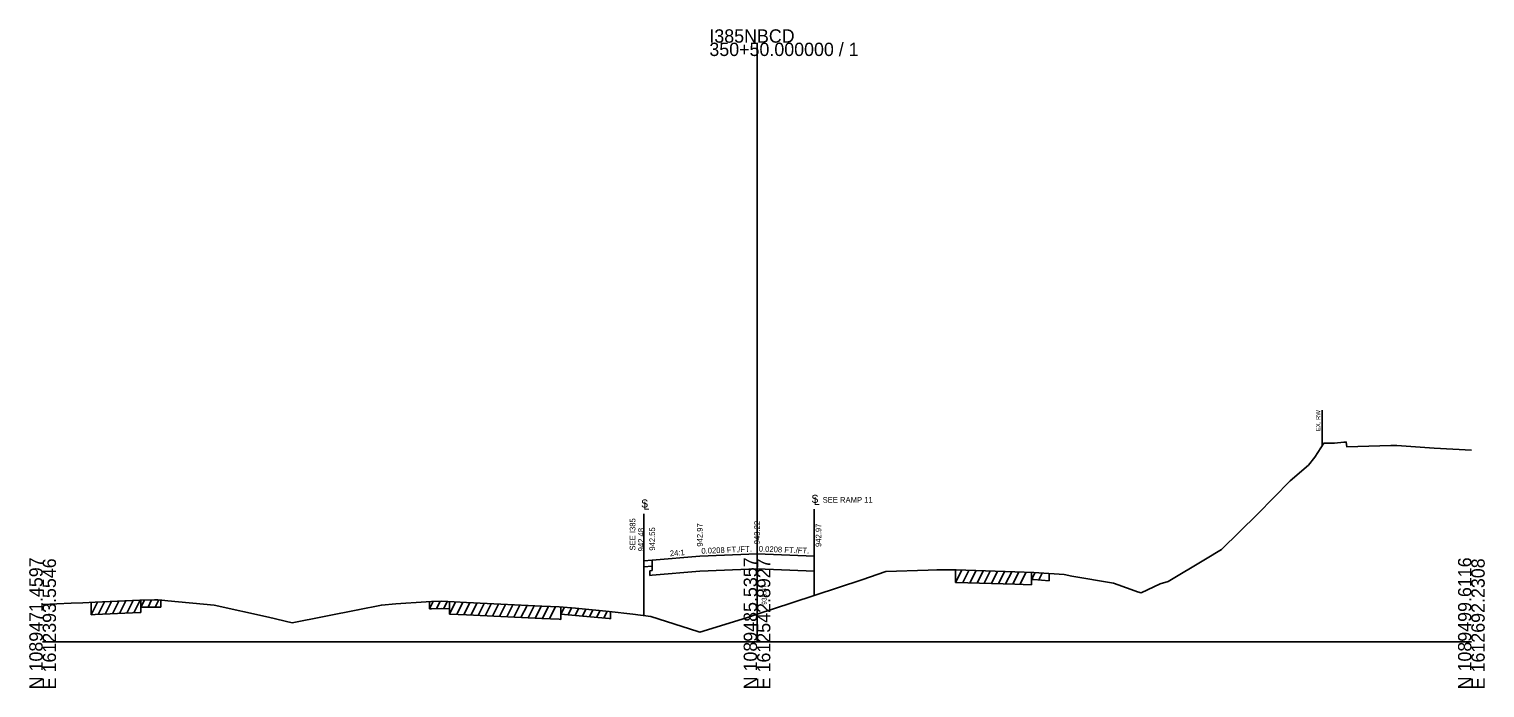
# Model space of a CAD drawing. Extents: x -26 to 1613369, y -10 to 1281970.
# Drawn here: x 997.2 to 1302.8, y -9.7 to 128.6 of the extents above; entities that cross this region are included whole.
import ezdxf

# ---------------------------------------------------------------- set-up
doc = ezdxf.new("R2010")
doc.units = 0
for name, color, linetype in [('RD_EX_Misc', 7, 'Continuous'), ('RD_GPK_XS_Cell', 7, 'Continuous'), ('RD_Sketch1', 7, 'Continuous'), ('RD_XS_Base', 7, 'Continuous'), ('RD_XS_Box', 7, 'Continuous'), ('RD_XS_ExGround', 7, 'Continuous'), ('RD_XS_ExPaveRet', 7, 'Continuous'), ('RD_XS_ExRW', 7, 'Continuous'), ('RD_XS_MatchLine', 7, 'Continuous'), ('RD_XS_OSBase', 7, 'Continuous'), ('RD_XS_Pave', 7, 'Continuous'), ('RD_XS_PaveShd', 7, 'Continuous'), ('RD_XS_TX_Elev_EX', 7, 'Continuous'), ('RD_XS_TX_Elev_PR', 7, 'Continuous'), ('RD_XS_TX_MatchLine', 7, 'Continuous'), ('RD_XS_TX_Notes', 7, 'Continuous'), ('RD_XS_TX_ShdSlope', 7, 'Continuous'), ('RD_XS_TX_Slope', 7, 'Continuous')]:
    doc.layers.add(name, color=color, linetype=linetype)

msp = doc.modelspace()

# ---------------------------------------------------------------- linework, layer by layer
at = {"layer": 'RD_EX_Misc'}
for p, q in [((1207.65, 13.05), (1207.65, 14.55)), ((1207.65, 13.05), (1208.11, 13.04)), ((1208.11, 13.04), (1211.37, 12.8)), ((1211.37, 14.3), (1211.37, 12.8)), ((1020.63, 7.24), (1020.63, 8.74)), ((1020.63, 7.24), (1023.52, 7.25)), ((1023.52, 7.25), (1024.21, 7.26)), ((1024.21, 7.26), (1024.82, 7.22)), ((1024.82, 8.72), (1024.82, 7.22)), ((1081.22, 6.88), (1081.22, 8.38)), ((1081.22, 6.88), (1081.68, 6.9)), ((1081.68, 6.9), (1083.85, 6.97)), ((1083.85, 6.97), (1085.44, 6.9)), ((1085.44, 8.4), (1085.44, 6.9)), ((1108.83, 5.79), (1108.83, 7.29)), ((1119.25, 6.31), (1119.25, 4.81)), ((1108.83, 5.79), (1111.9, 5.5)), ((1111.9, 5.5), (1118.96, 4.85)), ((1118.96, 4.85), (1119.25, 4.81))]:
    msp.add_line(p, q, dxfattribs=at)
at = {"layer": 'RD_GPK_XS_Cell'}
for p, q in [((1150, 0), (1150, 125.71)), ((1000, 0), (1150, 0)), ((1150, 0), (1300, 0))]:
    msp.add_line(p, q, dxfattribs=at)
at = {"layer": 'RD_Sketch1'}
for p, q in [((1207.65, 13.05), (1208.39, 14.52)), ((1209.15, 12.96), (1209.88, 14.41)), ((1020.63, 7.24), (1021.38, 8.74)), ((1022.13, 7.24), (1022.88, 8.75)), ((1023.63, 7.25), (1024.37, 8.75)), ((1081.22, 6.88), (1081.98, 8.41)), ((1082.72, 6.93), (1083.48, 8.46)), ((1084.22, 6.96), (1084.95, 8.42)), ((1108.83, 5.79), (1109.55, 7.22)), ((1110.33, 5.65), (1111.05, 7.08)), ((1111.83, 5.51), (1112.55, 6.94)), ((1113.33, 5.37), (1114.05, 6.8)), ((1114.83, 5.23), (1115.55, 6.66)), ((1116.33, 5.09), (1117.05, 6.52)), ((1117.83, 4.95), (1118.55, 6.38))]:
    msp.add_line(p, q, dxfattribs=at)
at = {"layer": 'RD_XS_Base'}
for p, q in [((1128, 17.1), (1128, 14.94)), ((1128, 14.94), (1127.5, 14.9)), ((1127.5, 14.9), (1127.5, 13.9)), ((1128, 13.94), (1127.5, 13.9)), ((1138, 14.77), (1128, 13.94)), ((1150, 15.27), (1138, 14.77)), ((1150, 15.27), (1162, 14.77))]:
    msp.add_line(p, q, dxfattribs=at)
at = {"layer": 'RD_XS_Box'}
msp.add_line((1128, 17.1), (1126.24, 16.96), dxfattribs=at)
at = {"layer": 'RD_XS_ExGround'}
msp.add_lwpolyline([(1000, 7.78), (1005.97, 8.06), (1008.46, 8.17), (1011.05, 8.3), (1020.41, 8.74), (1023.52, 8.75), (1024.21, 8.76), (1025.02, 8.71), (1026.3, 8.55), (1035.99, 7.66), (1047.41, 5.13), (1052.37, 3.96), (1066.19, 6.68), (1071.12, 7.69), (1074.14, 7.92), (1080.5, 8.36), (1081.68, 8.4), (1083.85, 8.47), (1089.01, 8.23), (1096.19, 7.86), (1104.8, 7.48), (1108.43, 7.32), (1111.9, 7), (1118.96, 6.35), (1123.95, 5.74), (1127.71, 5.31), (1137.59, 2.17), (1138.01, 2.03), (1147.76, 5), (1150, 5.74), (1157.3, 8.14), (1171.98, 12.99), (1177.06, 14.73), (1185.96, 15.01), (1187.74, 15.08), (1191.82, 15.05), (1204.12, 14.66), (1208.11, 14.54), (1214.48, 14.08), (1216.13, 13.78), (1224.84, 12.31), (1228.6, 10.95), (1229.9, 10.49), (1230.64, 10.26), (1234.63, 12.17), (1236.33, 12.63), (1244.14, 17.35), (1247.55, 19.33), (1255.11, 26.73), (1261.94, 33.79), (1265.78, 37.06), (1267.13, 38.74), (1269.02, 41.63), (1271.24, 41.67), (1273.22, 41.9), (1273.73, 41.9), (1273.83, 40.9), (1283.08, 41.14), (1284.32, 41.14), (1292.19, 40.64), (1300, 40.18)], dxfattribs=at)
at = {"layer": 'RD_XS_ExPaveRet'}
for p, q in [((1191.71, 12.45), (1191.71, 15.05)), ((1191.71, 12.45), (1192.99, 15.01)), ((1191.71, 12.45), (1191.82, 12.45)), ((1191.82, 12.45), (1204.12, 12.06)), ((1193.21, 12.41), (1194.49, 14.97)), ((1194.71, 12.36), (1195.99, 14.92)), ((1196.21, 12.31), (1197.49, 14.87)), ((1197.71, 12.26), (1198.99, 14.82)), ((1199.21, 12.22), (1200.49, 14.78)), ((1200.71, 12.17), (1201.99, 14.73)), ((1202.21, 12.12), (1203.49, 14.68)), ((1203.71, 12.08), (1204.99, 14.64)), ((1205.21, 12.03), (1206.49, 14.59)), ((1207.65, 14.55), (1207.65, 11.95)), ((1204.12, 12.06), (1207.65, 11.95)), ((1010.16, 5.65), (1011.49, 8.32)), ((1010.16, 5.65), (1010.16, 8.25)), ((1011.05, 5.7), (1020.41, 6.14)), ((1011.66, 5.73), (1012.99, 8.39)), ((1013.16, 5.8), (1014.49, 8.46)), ((1014.66, 5.87), (1015.99, 8.53)), ((1016.16, 5.94), (1017.49, 8.6)), ((1017.66, 6.01), (1018.99, 8.67)), ((1019.16, 6.08), (1020.49, 8.74)), ((1020.41, 6.14), (1020.63, 6.14)), ((1020.63, 8.74), (1020.63, 6.14)), ((1085.44, 5.8), (1085.44, 8.4)), ((1085.44, 5.8), (1086.71, 8.34)), ((1086.94, 5.73), (1088.21, 8.27)), ((1088.44, 5.66), (1089.71, 8.19)), ((1089.94, 5.58), (1091.21, 8.12)), ((1091.44, 5.51), (1092.71, 8.04)), ((1092.94, 5.43), (1094.21, 7.96)), ((1094.44, 5.35), (1095.71, 7.89)), ((1095.94, 5.28), (1097.22, 7.82)), ((1097.44, 5.21), (1098.72, 7.75)), ((1098.94, 5.14), (1100.22, 7.69)), ((1100.44, 5.08), (1101.72, 7.62)), ((1101.94, 5.01), (1103.22, 7.55)), ((1103.44, 4.94), (1104.72, 7.49)), ((1104.94, 4.88), (1106.22, 7.42)), ((1106.44, 4.81), (1107.72, 7.36)), ((1108.83, 7.29), (1108.83, 4.69)), ((1010.16, 5.65), (1011.05, 5.7)), ((1085.44, 5.8), (1089.01, 5.63)), ((1089.01, 5.63), (1096.19, 5.26)), ((1096.19, 5.26), (1104.8, 4.88)), ((1104.8, 4.88), (1108.43, 4.72)), ((1108.43, 4.72), (1108.83, 4.69))]:
    msp.add_line(p, q, dxfattribs=at)
at = {"layer": 'RD_XS_ExRW'}
msp.add_line((1268.64, 48.58), (1268.64, 41.06), dxfattribs=at)
at = {"layer": 'RD_XS_MatchLine'}
for p, q in [((1126.24, 5.48), (1126.24, 16.96)), ((1162, 9.69), (1162, 17.94))]:
    msp.add_line(p, q, dxfattribs=at)
at = {"layer": 'RD_XS_OSBase'}
for p, q in [((1126.24, 15.72), (1126.24, 16.96)), ((1128, 15.86), (1126.24, 15.72)), ((1128, 17.1), (1128, 15.86))]:
    msp.add_line(p, q, dxfattribs=at)
at = {"layer": 'RD_XS_Pave'}
for q in [(1138, 17.94), (1162, 17.94)]:
    msp.add_line((1150, 18.44), q, dxfattribs=at)
at = {"layer": 'RD_XS_PaveShd'}
msp.add_line((1138, 17.94), (1128, 17.1), dxfattribs=at)
at = {"layer": 'RD_XS_TX_MatchLine'}
for p, q in [((1162, 17.94), (1162, 27.82)), ((1126.24, 16.96), (1126.24, 26.84)), ((1126.24, 11.96), (1126.24, 16.96)), ((1162, 12.94), (1162, 17.94))]:
    msp.add_line(p, q, dxfattribs=at)

# ---------------------------------------------------------------- texts
at = {"layer": 'RD_GPK_XS_Cell'}
for s, p in [('I385NBCD', (1140, 125.71)), ('350+50.000000 / 1', (1140, 122.91))]:
    msp.add_text(s, height=2.8, dxfattribs=at).set_placement(p)
for s, p in [('N 1089471.4597', (1000, -10)), ('E 1612393.5546', (1002.8, -10)), ('N 1089485.5357', (1150, -10)), ('E 1612542.8927', (1152.8, -10)), ('N 1089499.6116', (1300, -10)), ('E 1612692.2308', (1302.8, -10))]:
    msp.add_text(s, height=2.8, rotation=90, dxfattribs=at).set_placement(p)
at = {"layer": 'RD_XS_ExRW'}
msp.add_text('EX. RW', height=0.9, rotation=90, dxfattribs=at).set_placement((1268.28, 44.18))
at = {"layer": 'RD_XS_TX_Elev_EX'}
msp.add_text('936.87', height=1, rotation=90, dxfattribs=at).set_placement((1152, 7.74))
at = {"layer": 'RD_XS_TX_Elev_PR'}
for s, p in [('942.97', (1138.6, 19.94)), ('943.22', (1150.6, 20.44)), ('942.97', (1163.5, 19.88)), ('942.48', (1126.24, 18.96)), ('942.55', (1128.6, 19.1))]:
    msp.add_text(s, height=1.2, rotation=90, dxfattribs=at).set_placement(p)
at = {"layer": 'RD_XS_TX_MatchLine'}
for s, p in [('S', (1161.42, 29.14)), ('S', (1125.66, 28.16)), ('L', (1126.17, 27.72)), ('L', (1161.93, 28.7))]:
    msp.add_text(s, height=1.68, dxfattribs=at).set_placement(p)
at = {"layer": 'RD_XS_TX_Notes'}
msp.add_text('SEE RAMP 11', height=1.2, dxfattribs=at).set_placement((1163.78, 29.16))
msp.add_text('SEE I385', height=1.2, rotation=90, dxfattribs=at).set_placement((1124.47, 19.13))
at = {"layer": 'RD_XS_TX_ShdSlope'}
msp.add_text('24:1', height=1.2, rotation=4.7636, dxfattribs=at).set_placement((1131.75, 17.92))
at = {"layer": 'RD_XS_TX_Slope'}
for rotation, p in [(2.3859, (1138.34, 18.45)), (357.6141, (1150.35, 18.92))]:
    msp.add_text('0.0208 FT./FT.', height=1.2, rotation=rotation, dxfattribs=at).set_placement(p)

doc.saveas('drawing.dxf')
